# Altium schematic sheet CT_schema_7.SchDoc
size 278 x 170 mm
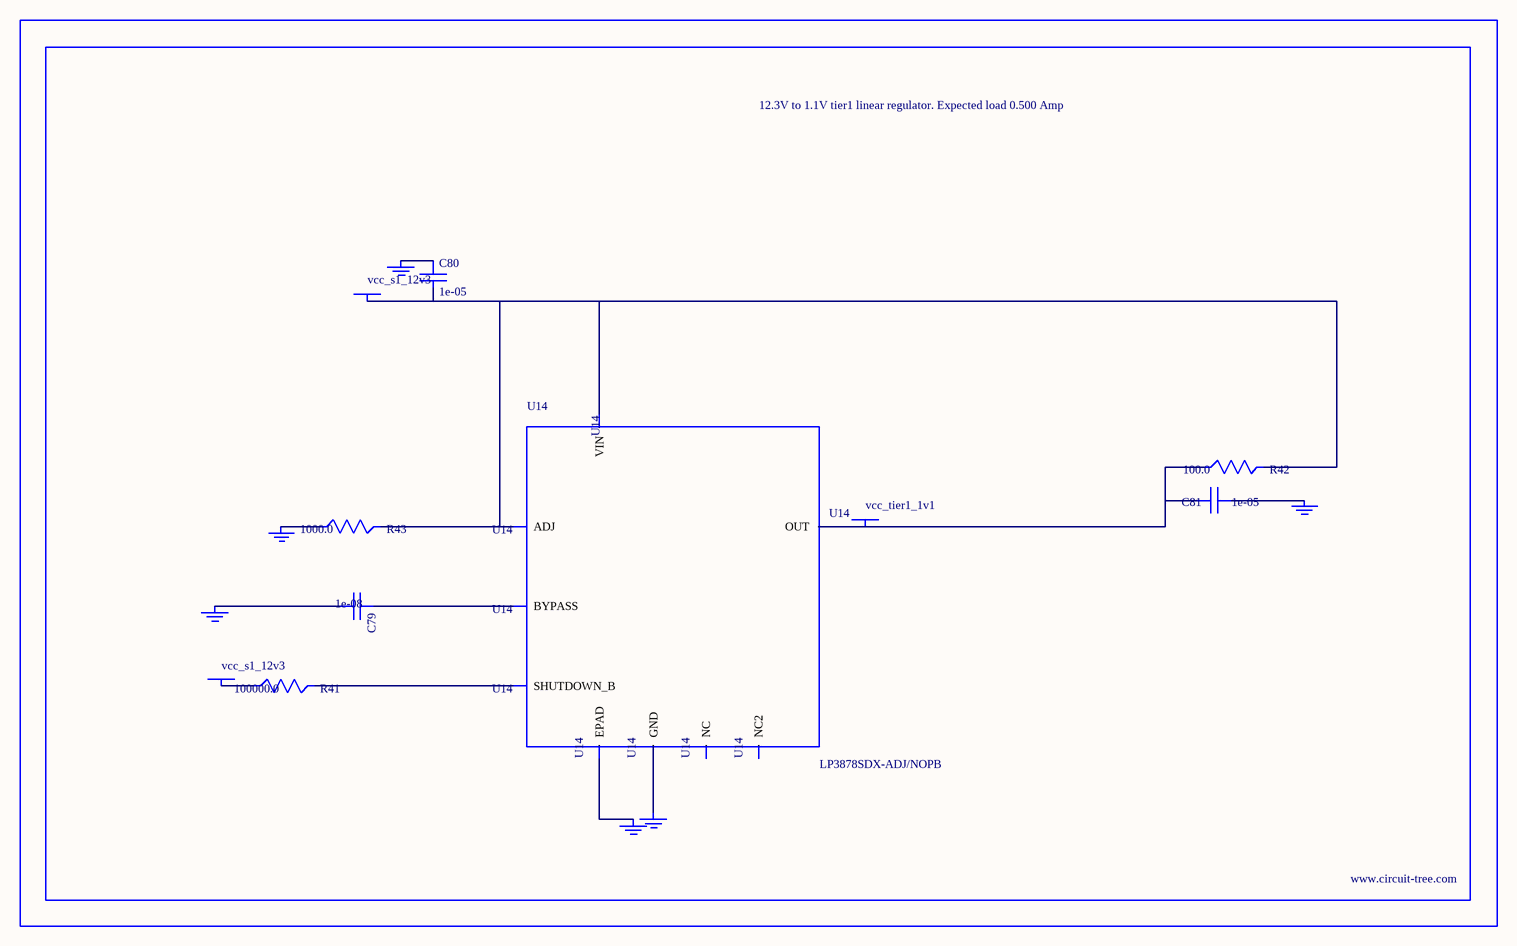
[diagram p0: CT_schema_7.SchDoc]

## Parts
BORDER6  (no value)
C79  1e-08  [C0402]
C80  1e-05  [C1210]
C81  1e-05  [C0805]
GND_INSTANCE_6_0  (no value)
GND_INSTANCE_6_1  (no value)
GND_INSTANCE_6_2  (no value)
GND_INSTANCE_6_3  (no value)
GND_INSTANCE_6_4  (no value)
GND_INSTANCE_6_5  (no value)
POWER_INSTANCE_6_0  vcc_s1_12v3
POWER_INSTANCE_6_1  vcc_s1_12v3
POWER_INSTANCE_6_2  vcc_tier1_1v1
R41  100000.0  [R0603]
R42  100.0  [R0603]
R43  1000.0  [R0603]
U14  LP3878SDX-ADJ/NOPB  [WSON-8]

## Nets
NetC79_1: C79.1 U14.1(BYPASS)
NetC79_2: C79.2 GND_INSTANCE_6_0.0(GND)
NetC80_1: C80.1 GND_INSTANCE_6_1.0(GND)
NetC80_2: C80.2 POWER_INSTANCE_6_0.0(PWR) R42.2 R43.2 U14.4(VIN) U14.6(ADJ)
NetC81_1: C81.1 GND_INSTANCE_6_2.0(GND)
NetC81_2: C81.2 POWER_INSTANCE_6_2.0(PWR) R42.1 U14.5(OUT)
NetGND_INSTANCE_6_3_0: GND_INSTANCE_6_3.0(GND) R43.1
NetGND_INSTANCE_6_4_0: GND_INSTANCE_6_4.0(GND) U14.PAD(EPAD)
NetGND_INSTANCE_6_5_0: GND_INSTANCE_6_5.0(GND) U14.3(GND)
NetPOWER_INSTANCE_6_1_0: POWER_INSTANCE_6_1.0(PWR) R41.1
NetR41_2: R41.2 U14.8(SHUTDOWN_B)

Not connected (* = marked no-connect by the designer): U14 2(NC) 7(NC2)

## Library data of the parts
BORDER6 = BORDER_PAGE6
C79 = C0402C103K3RAC
C80 = C1210C106K5PACTU
C81 = GRM219R60J106ME19D
GND_INSTANCE_6_0-GND_INSTANCE_6_5 = GND
POWER_INSTANCE_6_0-POWER_INSTANCE_6_2 = PWR
R41 = RC0603JR-07100KL
R42 = RC0603JR-07100RL
R43 = RC0603JR-071KL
